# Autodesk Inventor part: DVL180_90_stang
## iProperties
Created: 2009-09
Part Number: DVL180_90_stang
Document SubType Name: Modeling
Designer: TB
Mass: 3059.02 g
Surface Area: 1565.14 cm^2
Volume: 3059.02 cm^3
Density: 1 g/cm^3
Author: TB
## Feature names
1. Revolution1
2. Fillet1
3. Revolution2
